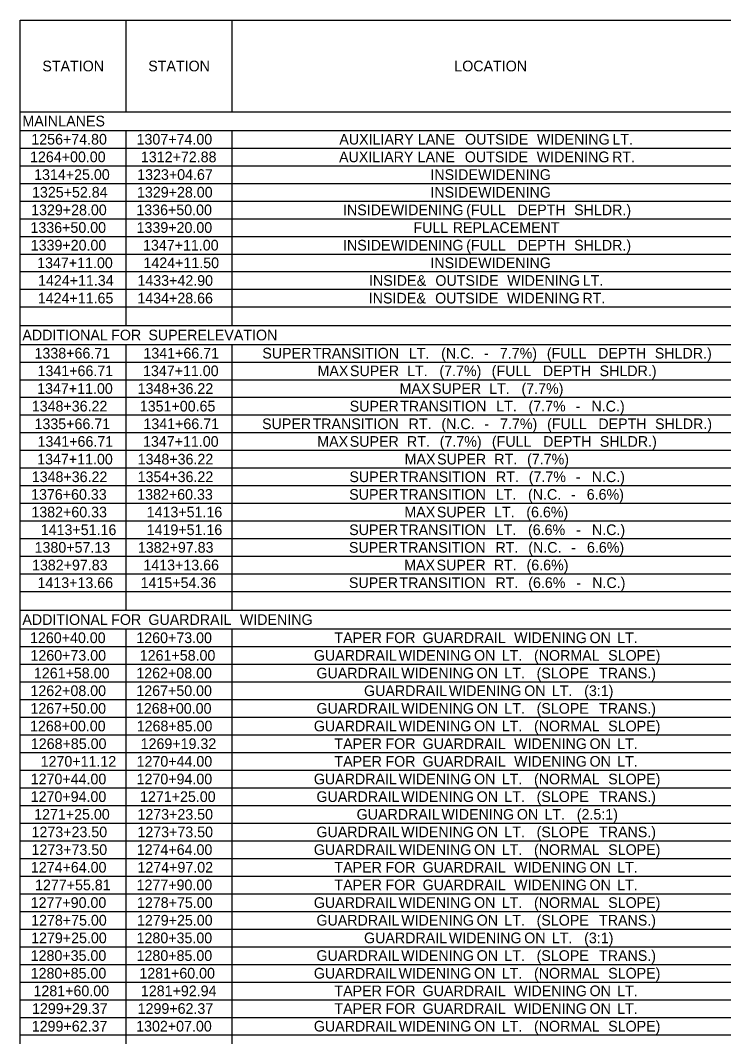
# Model space of a CAD drawing. Extents: x 1226590 to 1228573, y 151304 to 154224.
# Drawn here: x 1226590.3 to 1226850.3, y 151806.5 to 152182 of the extents above; entities that cross this region are included whole.
import ezdxf

# ---------------------------------------------------------------- set-up
doc = ezdxf.new("R2010")
doc.units = 0
doc.layers.add('R_Dimension', color=7, linetype='Continuous')

msp = doc.modelspace()

# ---------------------------------------------------------------- linework, layer by layer
at = {"layer": 'R_Dimension'}
for p, q in [((1226590.27, 152182.03), (1228150.73, 152182.03)), ((1226590.27, 151484.92), (1226590.27, 152182.03)), ((1226629.41, 152148.27), (1226629.41, 152182.03)), ((1226668.54, 152148.27), (1226668.54, 152182.03)), ((1226590.27, 152148.27), (1228150.73, 152148.27)), ((1226590.27, 152141.36), (1228150.73, 152141.36)), ((1226629.41, 152069.23), (1226629.41, 152141.36)), ((1226668.54, 152069.23), (1226668.54, 152141.36)), ((1226590.27, 152134.84), (1228150.73, 152134.84)), ((1226590.27, 152128.31), (1228150.73, 152128.31)), ((1226590.27, 152121.79), (1228150.73, 152121.79)), ((1226590.27, 152115.27), (1228150.73, 152115.27)), ((1226590.27, 152108.75), (1228150.73, 152108.75)), ((1226590.27, 152102.22), (1228150.73, 152102.22)), ((1226590.27, 152095.7), (1228150.73, 152095.7)), ((1226590.27, 152089.18), (1228150.73, 152089.18)), ((1226590.27, 152082.65), (1228150.73, 152082.65)), ((1226590.27, 152076.13), (1228150.73, 152076.13)), ((1226590.27, 152069.23), (1228150.73, 152069.23)), ((1226590.27, 152062.32), (1228150.73, 152062.32)), ((1226629.41, 151964.1), (1226629.41, 152062.32)), ((1226668.54, 151964.1), (1226668.54, 152062.32)), ((1226590.27, 152055.8), (1228150.73, 152055.8)), ((1226590.27, 152049.27), (1228150.73, 152049.27)), ((1226590.27, 152042.75), (1228150.73, 152042.75)), ((1226590.27, 152036.23), (1228150.73, 152036.23)), ((1226590.27, 152029.71), (1228150.73, 152029.71)), ((1226590.27, 152023.18), (1228150.73, 152023.18)), ((1226590.27, 152016.66), (1228150.73, 152016.66)), ((1226590.27, 152010.14), (1228150.73, 152010.14)), ((1226590.27, 152003.61), (1228150.73, 152003.61)), ((1226590.27, 151997.09), (1228150.73, 151997.09)), ((1226590.27, 151990.57), (1228150.73, 151990.57)), ((1226590.27, 151984.05), (1228150.73, 151984.05)), ((1226590.27, 151977.52), (1228150.73, 151977.52)), ((1226590.27, 151971), (1228150.73, 151971)), ((1226590.27, 151964.1), (1228150.73, 151964.1)), ((1226590.27, 151957.19), (1228150.73, 151957.19)), ((1226629.41, 151500.6), (1226629.41, 151957.19)), ((1226668.54, 151500.6), (1226668.54, 151957.19)), ((1226590.27, 151950.67), (1228150.73, 151950.67)), ((1226590.27, 151944.14), (1228150.73, 151944.14)), ((1226590.27, 151937.62), (1228150.73, 151937.62)), ((1226590.27, 151931.1), (1228150.73, 151931.1)), ((1226590.27, 151924.58), (1228150.73, 151924.58)), ((1226590.27, 151918.05), (1228150.73, 151918.05)), ((1226590.27, 151911.53), (1228150.73, 151911.53)), ((1226590.27, 151905.01), (1228150.73, 151905.01)), ((1226590.27, 151898.48), (1228150.73, 151898.48)), ((1226590.27, 151891.96), (1228150.73, 151891.96)), ((1226590.27, 151885.44), (1228150.73, 151885.44)), ((1226590.27, 151878.92), (1228150.73, 151878.92)), ((1226590.27, 151872.39), (1228150.73, 151872.39)), ((1226590.27, 151865.87), (1228150.73, 151865.87)), ((1226590.27, 151859.35), (1228150.73, 151859.35)), ((1226590.27, 151852.83), (1228150.73, 151852.83)), ((1226590.27, 151846.3), (1228150.73, 151846.3)), ((1226590.27, 151839.78), (1228150.73, 151839.78)), ((1226590.27, 151833.26), (1228150.73, 151833.26)), ((1226590.27, 151826.73), (1228150.73, 151826.73)), ((1226590.27, 151820.21), (1228150.73, 151820.21)), ((1226590.27, 151813.69), (1228150.73, 151813.69)), ((1226590.27, 151807.17), (1228150.73, 151807.17))]:
    msp.add_line(p, q, dxfattribs=at)

# ---------------------------------------------------------------- texts
for s, height, p in [('STATION', 3.935, (1226598.42, 152163.18)), ('STATION', 3.935, (1226637.56, 152163.18)), ('LOCATION', 3.935, (1226750.7, 152163.18)), ('MAIN', 3.935, (1226591.04, 152142.84)), (' LANES', 3.935, (1226602.84, 152142.84)), ('1256+74.80', 3.935, (1226594.33, 152136.13)), ('1307+74.00', 3.935, (1226633.25, 152136.13)), ('AUXILIARY', 3.935, (1226708.19, 152136.13)), (' LANE', 3.935, (1226735.77, 152136.13)), (' OUTSIDE', 3.935, (1226753.21, 152136.13)), (' WIDENING', 3.935, (1226779.77, 152136.13)), (' LT.', 3.935, (1226807.66, 152136.13)), ('1264+00.00', 3.935, (1226593.86, 152129.61)), ('1312+72.88', 3.935, (1226634.84, 152129.61)), ('AUXILIARY', 3.935, (1226708.1, 152129.61)), (' LANE', 3.935, (1226735.68, 152129.61)), (' OUTSIDE', 3.935, (1226753.12, 152129.61)), (' WIDENING', 3.935, (1226779.68, 152129.61)), (' RT.', 3.935, (1226807.56, 152129.61)), ('1314+25.00', 3.935, (1226595.38, 152123.08)), ('1323+04.67', 3.935, (1226633.48, 152123.08)), ('INSIDE', 3.935, (1226741.86, 152123.08)), (' WIDENING', 3.935, (1226758.03, 152123.08)), ('1325+52.84', 3.935, (1226594.59, 152116.56)), ('1329+28.00', 3.935, (1226633.4, 152116.56)), ('INSIDE', 3.935, (1226741.86, 152116.56)), (' WIDENING', 3.935, (1226758.03, 152116.56)), ('1329+28.00', 3.935, (1226594.27, 152110.04)), ('1336+50.00', 3.935, (1226633.16, 152110.04)), ('INSIDE', 3.935, (1226709.55, 152110.04)), (' WIDENING', 3.935, (1226725.73, 152110.04)), (' (FULL', 3.935, (1226753.62, 152110.04)), (' DEPTH', 3.935, (1226772.55, 152110.04)), (' SHLDR.)', 3.935, (1226793.53, 152110.04)), ('1336+50.00', 3.935, (1226594.02, 152103.52)), ('1339+20.00', 3.935, (1226633.25, 152103.52)), ('FULL', 3.935, (1226735.57, 152103.52)), (' REPLACEMENT', 3.9353, (1226748.64, 152103.52)), ('1339+20.00', 3.935, (1226594.11, 152096.99)), ('1347+11.00', 3.935, (1226635.63, 152096.99)), ('INSIDE', 3.935, (1226709.55, 152096.99)), (' WIDENING', 3.935, (1226725.73, 152096.99)), (' (FULL', 3.935, (1226753.62, 152096.99)), (' DEPTH', 3.935, (1226772.55, 152096.99)), (' SHLDR.)', 3.935, (1226793.53, 152096.99)), ('1347+11.00', 3.935, (1226596.5, 152090.47)), ('1424+11.50', 3.935, (1226635.79, 152090.47)), ('INSIDE', 3.935, (1226741.86, 152090.47)), (' WIDENING', 3.935, (1226758.03, 152090.47)), ('1424+11.34', 3.935, (1226596.82, 152083.95)), ('1433+42.90', 3.935, (1226633.56, 152083.95)), ('INSIDE', 3.935, (1226719.16, 152083.95)), (' &', 3.935, (1226735.33, 152083.95)), (' OUTSIDE', 3.935, (1226742.24, 152083.95)), (' WIDENING', 3.935, (1226768.8, 152083.95)), (' LT.', 3.935, (1226796.69, 152083.95)), ('1424+11.65', 3.935, (1226596.73, 152077.43)), ('1434+28.66', 3.935, (1226633.53, 152077.43)), ('INSIDE', 3.935, (1226719.07, 152077.43)), (' &', 3.935, (1226735.24, 152077.43)), (' OUTSIDE', 3.935, (1226742.15, 152077.43)), (' WIDENING', 3.935, (1226768.71, 152077.43)), (' RT.', 3.935, (1226796.59, 152077.43)), ('ADDITIONAL', 3.935, (1226591.04, 152063.8)), (' FOR', 3.935, (1226622.4, 152063.8)), (' SUPERELEVATION', 3.9353, (1226636.15, 152063.8)), ('1338+66.71', 3.935, (1226595.52, 152057.09)), ('1341+66.71', 3.935, (1226635.77, 152057.09)), ('SUPER', 3.935, (1226679.73, 152057.09)), (' TRANSITION', 3.9353, (1226696.93, 152057.09)), (' LT.', 3.935, (1226732.44, 152057.09)), (' (N.C.', 3.935, (1226744.37, 152057.09)), (' -', 3.935, (1226760.2, 152057.09)), (' 7.7%)', 3.935, (1226766.06, 152057.09)), (' (FULL', 3.935, (1226783.44, 152057.09)), (' DEPTH', 3.935, (1226802.37, 152057.09)), (' SHLDR.)', 3.935, (1226823.35, 152057.09)), (' (7.7%)', 3.935, (1226743.73, 152050.57)), (' (FULL', 3.935, (1226763.04, 152050.57)), (' SHLDR.)', 3.935, (1226802.95, 152050.57)), ('1341+66.71', 3.935, (1226596.64, 152050.57)), ('1347+11.00', 3.935, (1226635.63, 152050.57)), ('MAX', 3.935, (1226700.13, 152050.57)), (' SUPER', 3.935, (1226710.67, 152050.57)), (' LT.', 3.935, (1226731.8, 152050.57)), (' DEPTH', 3.935, (1226781.97, 152050.57)), ('1347+11.00', 3.935, (1226596.5, 152044.04)), ('1348+36.22', 3.935, (1226633.64, 152044.04)), ('MAX', 3.935, (1226730.47, 152044.04)), (' SUPER', 3.935, (1226741.01, 152044.04)), (' LT.', 3.935, (1226762.14, 152044.04)), (' (7.7%)', 3.935, (1226774.07, 152044.04)), ('1348+36.22', 3.935, (1226594.5, 152037.52)), ('1351+00.65', 3.935, (1226634.44, 152037.52)), ('SUPER', 3.935, (1226712.02, 152037.52)), (' TRANSITION', 3.9353, (1226729.22, 152037.52)), (' LT.', 3.935, (1226764.73, 152037.52)), (' (7.7%', 3.935, (1226776.66, 152037.52)), (' N.C.)', 3.935, (1226799.93, 152037.52)), (' -', 3.935, (1226794.07, 152037.52)), ('1335+66.71', 3.935, (1226595.52, 152031)), ('1341+66.71', 3.935, (1226635.77, 152031)), ('SUPER', 3.935, (1226679.64, 152031)), (' TRANSITION', 3.9353, (1226696.83, 152031)), (' RT.', 3.935, (1226732.34, 152031)), (' (N.C.', 3.935, (1226744.46, 152031)), (' -', 3.935, (1226760.29, 152031)), (' 7.7%)', 3.935, (1226766.15, 152031)), (' (FULL', 3.935, (1226783.53, 152031)), (' DEPTH', 3.935, (1226802.47, 152031)), (' SHLDR.)', 3.935, (1226823.44, 152031)), ('1341+66.71', 3.935, (1226596.64, 152024.48)), ('1347+11.00', 3.935, (1226635.63, 152024.48)), ('MAX', 3.935, (1226700.04, 152024.48)), (' SUPER', 3.935, (1226710.58, 152024.48)), (' RT.', 3.935, (1226731.71, 152024.48)), (' (7.7%)', 3.935, (1226743.83, 152024.48)), (' (FULL', 3.935, (1226763.13, 152024.48)), (' DEPTH', 3.935, (1226782.06, 152024.48)), (' SHLDR.)', 3.935, (1226803.04, 152024.48)), ('1347+11.00', 3.935, (1226596.5, 152017.95)), ('1348+36.22', 3.935, (1226633.64, 152017.95)), ('MAX', 3.935, (1226732.34, 152017.95)), (' SUPER', 3.935, (1226742.88, 152017.95)), (' RT.', 3.935, (1226764.01, 152017.95)), (' (7.7%)', 3.935, (1226776.13, 152017.95)), ('1348+36.22', 3.935, (1226594.5, 152011.43)), ('1354+36.22', 3.935, (1226633.64, 152011.43)), ('SUPER', 3.935, (1226711.92, 152011.43)), (' TRANSITION', 3.9353, (1226729.12, 152011.43)), (' RT.', 3.935, (1226764.63, 152011.43)), (' (7.7%', 3.935, (1226776.75, 152011.43)), (' N.C.)', 3.935, (1226800.02, 152011.43)), (' -', 3.935, (1226794.16, 152011.43)), ('1376+60.33', 3.935, (1226594.25, 152004.91)), ('1382+60.33', 3.935, (1226633.48, 152004.91)), ('SUPER', 3.935, (1226711.85, 152004.91)), (' TRANSITION', 3.9353, (1226729.04, 152004.91)), (' LT.', 3.935, (1226764.56, 152004.91)), (' (N.C.', 3.935, (1226776.48, 152004.91)), (' -', 3.935, (1226792.32, 152004.91)), (' 6.6%)', 3.935, (1226798.18, 152004.91)), ('1382+60.33', 3.935, (1226594.35, 151998.39)), ('1413+51.16', 3.935, (1226636.97, 151998.39)), ('MAX', 3.935, (1226732.25, 151998.39)), (' SUPER', 3.935, (1226742.79, 151998.39)), (' LT.', 3.935, (1226763.92, 151998.39)), (' (6.6%)', 3.935, (1226775.85, 151998.39)), ('1413+51.16', 3.935, (1226597.83, 151991.86)), ('1419+51.16', 3.935, (1226636.97, 151991.86)), ('SUPER', 3.935, (1226711.83, 151991.86)), (' TRANSITION', 3.9353, (1226729.03, 151991.86)), (' LT.', 3.935, (1226764.54, 151991.86)), (' (6.6%', 3.935, (1226776.47, 151991.86)), (' N.C.)', 3.935, (1226800.11, 151991.86)), (' -', 3.935, (1226794.26, 151991.86)), ('1380+57.13', 3.935, (1226595.55, 151985.34)), ('1382+97.83', 3.935, (1226633.73, 151985.34)), ('SUPER', 3.935, (1226711.75, 151985.34)), (' TRANSITION', 3.9353, (1226728.95, 151985.34)), (' RT.', 3.935, (1226764.46, 151985.34)), (' (N.C.', 3.935, (1226776.58, 151985.34)), (' -', 3.935, (1226792.41, 151985.34)), (' 6.6%)', 3.935, (1226798.27, 151985.34)), ('1382+97.83', 3.935, (1226594.59, 151978.82)), ('1413+13.66', 3.935, (1226635.76, 151978.82)), ('MAX', 3.935, (1226732.16, 151978.82)), (' SUPER', 3.935, (1226742.69, 151978.82)), (' RT.', 3.935, (1226763.83, 151978.82)), (' (6.6%)', 3.935, (1226775.94, 151978.82)), ('1413+13.66', 3.935, (1226596.62, 151972.3)), ('1415+54.36', 3.935, (1226634.74, 151972.3)), ('SUPER', 3.935, (1226711.74, 151972.3)), (' TRANSITION', 3.9353, (1226728.94, 151972.3)), (' RT.', 3.935, (1226764.45, 151972.3)), (' (6.6%', 3.935, (1226776.56, 151972.3)), (' N.C.)', 3.935, (1226800.2, 151972.3)), (' -', 3.935, (1226794.35, 151972.3)), ('ADDITIONAL', 3.935, (1226591.04, 151958.67)), (' FOR', 3.935, (1226622.4, 151958.67)), (' GUARDRAIL', 3.935, (1226636.15, 151958.67)), (' WIDENING', 3.935, (1226669.96, 151958.67)), ('1260+40.00', 3.935, (1226593.86, 151951.96)), ('1260+73.00', 3.935, (1226633.16, 151951.96)), ('TAPER', 3.935, (1226706.39, 151951.96)), (' FOR', 3.935, (1226723.78, 151951.96)), (' GUARDRAIL', 3.935, (1226737.53, 151951.96)), (' WIDENING', 3.935, (1226771.34, 151951.96)), (' ON', 3.935, (1226799.23, 151951.96)), (' LT.', 3.935, (1226809.45, 151951.96)), ('1260+73.00', 3.935, (1226594.02, 151945.44)), ('1261+58.00', 3.935, (1226634.43, 151945.44)), ('GUARDRAIL', 3.935, (1226698.77, 151945.44)), (' WIDENING', 3.935, (1226728.64, 151945.44)), (' ON', 3.935, (1226756.53, 151945.44)), (' (NORMAL', 3.935, (1226778.68, 151945.44)), (' SLOPE)', 3.935, (1226806.11, 151945.44)), (' LT.', 3.935, (1226766.76, 151945.44)), ('1261+58.00', 3.935, (1226595.29, 151938.91)), ('1262+08.00', 3.935, (1226633.16, 151938.91)), ('GUARDRAIL', 3.935, (1226699.73, 151938.91)), (' WIDENING', 3.935, (1226729.6, 151938.91)), (' ON', 3.935, (1226757.49, 151938.91)), (' LT.', 3.935, (1226767.72, 151938.91)), (' (SLOPE', 3.935, (1226779.65, 151938.91)), (' TRANS.)', 3.935, (1226802.73, 151938.91)), ('1262+08.00', 3.935, (1226594.02, 151932.39)), ('1267+50.00', 3.935, (1226633.16, 151932.39)), ('GUARDRAIL', 3.935, (1226717.32, 151932.39)), (' WIDENING', 3.935, (1226747.19, 151932.39)), (' ON', 3.935, (1226775.07, 151932.39)), (' LT.', 3.935, (1226785.3, 151932.39)), (' (3:1)', 3.935, (1226797.23, 151932.39)), ('1267+50.00', 3.935, (1226594.02, 151925.87)), ('1268+00.00', 3.935, (1226633, 151925.87)), ('GUARDRAIL', 3.935, (1226699.73, 151925.87)), (' WIDENING', 3.935, (1226729.6, 151925.87)), (' ON', 3.935, (1226757.49, 151925.87)), (' LT.', 3.935, (1226767.72, 151925.87)), (' (SLOPE', 3.935, (1226779.65, 151925.87)), (' TRANS.)', 3.935, (1226802.73, 151925.87)), ('1268+00.00', 3.935, (1226593.86, 151919.35)), ('1268+85.00', 3.935, (1226633.31, 151919.35)), ('GUARDRAIL', 3.935, (1226698.77, 151919.35)), (' WIDENING', 3.935, (1226728.64, 151919.35)), (' ON', 3.935, (1226756.53, 151919.35)), (' LT.', 3.935, (1226766.76, 151919.35)), (' (NORMAL', 3.935, (1226778.68, 151919.35)), (' SLOPE)', 3.935, (1226806.11, 151919.35)), ('1268+85.00', 3.935, (1226594.17, 151912.82)), ('1269+19.32', 3.935, (1226634.75, 151912.82)), ('TAPER', 3.935, (1226706.39, 151912.82)), (' FOR', 3.935, (1226723.78, 151912.82)), (' GUARDRAIL', 3.935, (1226737.53, 151912.82)), (' WIDENING', 3.935, (1226771.34, 151912.82)), (' ON', 3.935, (1226799.23, 151912.82)), (' LT.', 3.935, (1226809.45, 151912.82)), ('1270+11.12', 3.935, (1226597.78, 151906.3)), ('1270+44.00', 3.935, (1226633.25, 151906.3)), ('TAPER', 3.935, (1226706.39, 151906.3)), (' FOR', 3.935, (1226723.78, 151906.3)), (' GUARDRAIL', 3.935, (1226737.53, 151906.3)), (' WIDENING', 3.935, (1226771.34, 151906.3)), (' ON', 3.935, (1226799.23, 151906.3)), (' LT.', 3.935, (1226809.45, 151906.3)), ('1270+44.00', 3.935, (1226594.11, 151899.78)), ('1270+94.00', 3.935, (1226633.25, 151899.78)), ('GUARDRAIL', 3.935, (1226698.77, 151899.78)), (' WIDENING', 3.935, (1226728.64, 151899.78)), (' ON', 3.935, (1226756.53, 151899.78)), (' LT.', 3.935, (1226766.76, 151899.78)), (' (NORMAL', 3.935, (1226778.68, 151899.78)), (' SLOPE)', 3.935, (1226806.11, 151899.78)), ('1270+94.00', 3.935, (1226594.11, 151893.26)), ('1271+25.00', 3.935, (1226634.52, 151893.26)), ('GUARDRAIL', 3.935, (1226699.73, 151893.26)), (' WIDENING', 3.935, (1226729.6, 151893.26)), (' ON', 3.935, (1226757.49, 151893.26)), (' LT.', 3.935, (1226767.72, 151893.26)), (' (SLOPE', 3.935, (1226779.65, 151893.26)), (' TRANS.)', 3.935, (1226802.73, 151893.26)), ('1271+25.00', 3.935, (1226595.38, 151886.73)), ('1273+23.50', 3.935, (1226633.56, 151886.73)), ('GUARDRAIL', 3.935, (1226714.59, 151886.73)), (' WIDENING', 3.935, (1226744.46, 151886.73)), (' ON', 3.935, (1226772.35, 151886.73)), (' LT.', 3.935, (1226782.57, 151886.73)), (' (2.5:1)', 3.935, (1226794.5, 151886.73)), ('1273+23.50', 3.935, (1226594.42, 151880.21)), ('1273+73.50', 3.935, (1226633.56, 151880.21)), ('GUARDRAIL', 3.935, (1226699.73, 151880.21)), (' WIDENING', 3.935, (1226729.6, 151880.21)), (' ON', 3.935, (1226757.49, 151880.21)), (' LT.', 3.935, (1226767.72, 151880.21)), (' (SLOPE', 3.935, (1226779.65, 151880.21)), (' TRANS.)', 3.935, (1226802.73, 151880.21)), ('1273+73.50', 3.935, (1226594.42, 151873.69)), ('1274+64.00', 3.935, (1226633.31, 151873.69)), ('GUARDRAIL', 3.935, (1226698.77, 151873.69)), (' WIDENING', 3.935, (1226728.64, 151873.69)), (' ON', 3.935, (1226756.53, 151873.69)), (' LT.', 3.935, (1226766.76, 151873.69)), (' (NORMAL', 3.935, (1226778.68, 151873.69)), (' SLOPE)', 3.935, (1226806.11, 151873.69)), ('1274+64.00', 3.935, (1226594.17, 151867.16)), ('1274+97.02', 3.935, (1226633.57, 151867.16)), ('TAPER', 3.935, (1226706.39, 151867.16)), (' FOR', 3.935, (1226723.78, 151867.16)), (' GUARDRAIL', 3.935, (1226737.53, 151867.16)), (' WIDENING', 3.935, (1226771.34, 151867.16)), (' ON', 3.935, (1226799.23, 151867.16)), (' LT.', 3.935, (1226809.45, 151867.16)), ('1277+55.81', 3.935, (1226595.71, 151860.64)), ('1277+90.00', 3.935, (1226633.25, 151860.64)), ('TAPER', 3.935, (1226706.39, 151860.64)), (' FOR', 3.935, (1226723.78, 151860.64)), (' GUARDRAIL', 3.935, (1226737.53, 151860.64)), (' WIDENING', 3.935, (1226771.34, 151860.64)), (' ON', 3.935, (1226799.23, 151860.64)), (' LT.', 3.935, (1226809.45, 151860.64)), ('1277+90.00', 3.935, (1226594.11, 151854.12)), ('1278+75.00', 3.935, (1226633.4, 151854.12)), ('GUARDRAIL', 3.935, (1226698.77, 151854.12)), (' WIDENING', 3.935, (1226728.64, 151854.12)), (' ON', 3.935, (1226756.53, 151854.12)), (' LT.', 3.935, (1226766.76, 151854.12)), (' (NORMAL', 3.935, (1226778.68, 151854.12)), (' SLOPE)', 3.935, (1226806.11, 151854.12)), ('1278+75.00', 3.935, (1226594.27, 151847.6)), ('1279+25.00', 3.935, (1226633.4, 151847.6)), ('GUARDRAIL', 3.935, (1226699.73, 151847.6)), (' WIDENING', 3.935, (1226729.6, 151847.6)), (' ON', 3.935, (1226757.49, 151847.6)), (' LT.', 3.935, (1226767.72, 151847.6)), (' (SLOPE', 3.935, (1226779.65, 151847.6)), (' TRANS.)', 3.935, (1226802.73, 151847.6)), ('1279+25.00', 3.935, (1226594.27, 151841.07)), ('1280+35.00', 3.935, (1226633.25, 151841.07)), ('GUARDRAIL', 3.935, (1226717.32, 151841.07)), (' WIDENING', 3.935, (1226747.19, 151841.07)), (' ON', 3.935, (1226775.07, 151841.07)), (' LT.', 3.935, (1226785.3, 151841.07)), (' (3:1)', 3.935, (1226797.23, 151841.07)), ('1280+35.00', 3.935, (1226594.11, 151834.55)), ('1280+85.00', 3.935, (1226633.25, 151834.55)), ('GUARDRAIL', 3.935, (1226699.73, 151834.55)), (' WIDENING', 3.935, (1226729.6, 151834.55)), (' ON', 3.935, (1226757.49, 151834.55)), (' LT.', 3.935, (1226767.72, 151834.55)), (' (SLOPE', 3.935, (1226779.65, 151834.55)), (' TRANS.)', 3.935, (1226802.73, 151834.55)), ('1280+85.00', 3.935, (1226594.11, 151828.03)), ('1281+60.00', 3.935, (1226634.27, 151828.03)), ('GUARDRAIL', 3.935, (1226698.77, 151828.03)), (' WIDENING', 3.935, (1226728.64, 151828.03)), (' ON', 3.935, (1226756.53, 151828.03)), (' LT.', 3.935, (1226766.76, 151828.03)), (' (NORMAL', 3.935, (1226778.68, 151828.03)), (' SLOPE)', 3.935, (1226806.11, 151828.03)), ('1281+60.00', 3.935, (1226595.14, 151821.51)), ('1281+92.94', 3.935, (1226634.84, 151821.51)), ('TAPER', 3.935, (1226706.39, 151821.51)), (' FOR', 3.935, (1226723.78, 151821.51)), (' GUARDRAIL', 3.935, (1226737.53, 151821.51)), (' WIDENING', 3.935, (1226771.34, 151821.51)), (' ON', 3.935, (1226799.23, 151821.51)), (' LT.', 3.935, (1226809.45, 151821.51)), ('1299+29.37', 3.935, (1226594.59, 151814.98)), ('1299+62.37', 3.935, (1226633.64, 151814.98)), ('TAPER', 3.935, (1226706.39, 151814.98)), (' FOR', 3.935, (1226723.78, 151814.98)), (' GUARDRAIL', 3.935, (1226737.53, 151814.98)), (' WIDENING', 3.935, (1226771.34, 151814.98)), (' ON', 3.935, (1226799.23, 151814.98)), (' LT.', 3.935, (1226809.45, 151814.98)), ('1299+62.37', 3.935, (1226594.5, 151808.46)), ('1302+07.00', 3.935, (1226633.09, 151808.46)), ('GUARDRAIL', 3.935, (1226698.77, 151808.46)), (' WIDENING', 3.935, (1226728.64, 151808.46)), (' ON', 3.935, (1226756.53, 151808.46)), (' LT.', 3.935, (1226766.76, 151808.46)), (' (NORMAL', 3.935, (1226778.68, 151808.46)), (' SLOPE)', 3.935, (1226806.11, 151808.46))]:
    msp.add_text(s, height=height, dxfattribs=at).set_placement(p)

doc.saveas('drawing.dxf')
